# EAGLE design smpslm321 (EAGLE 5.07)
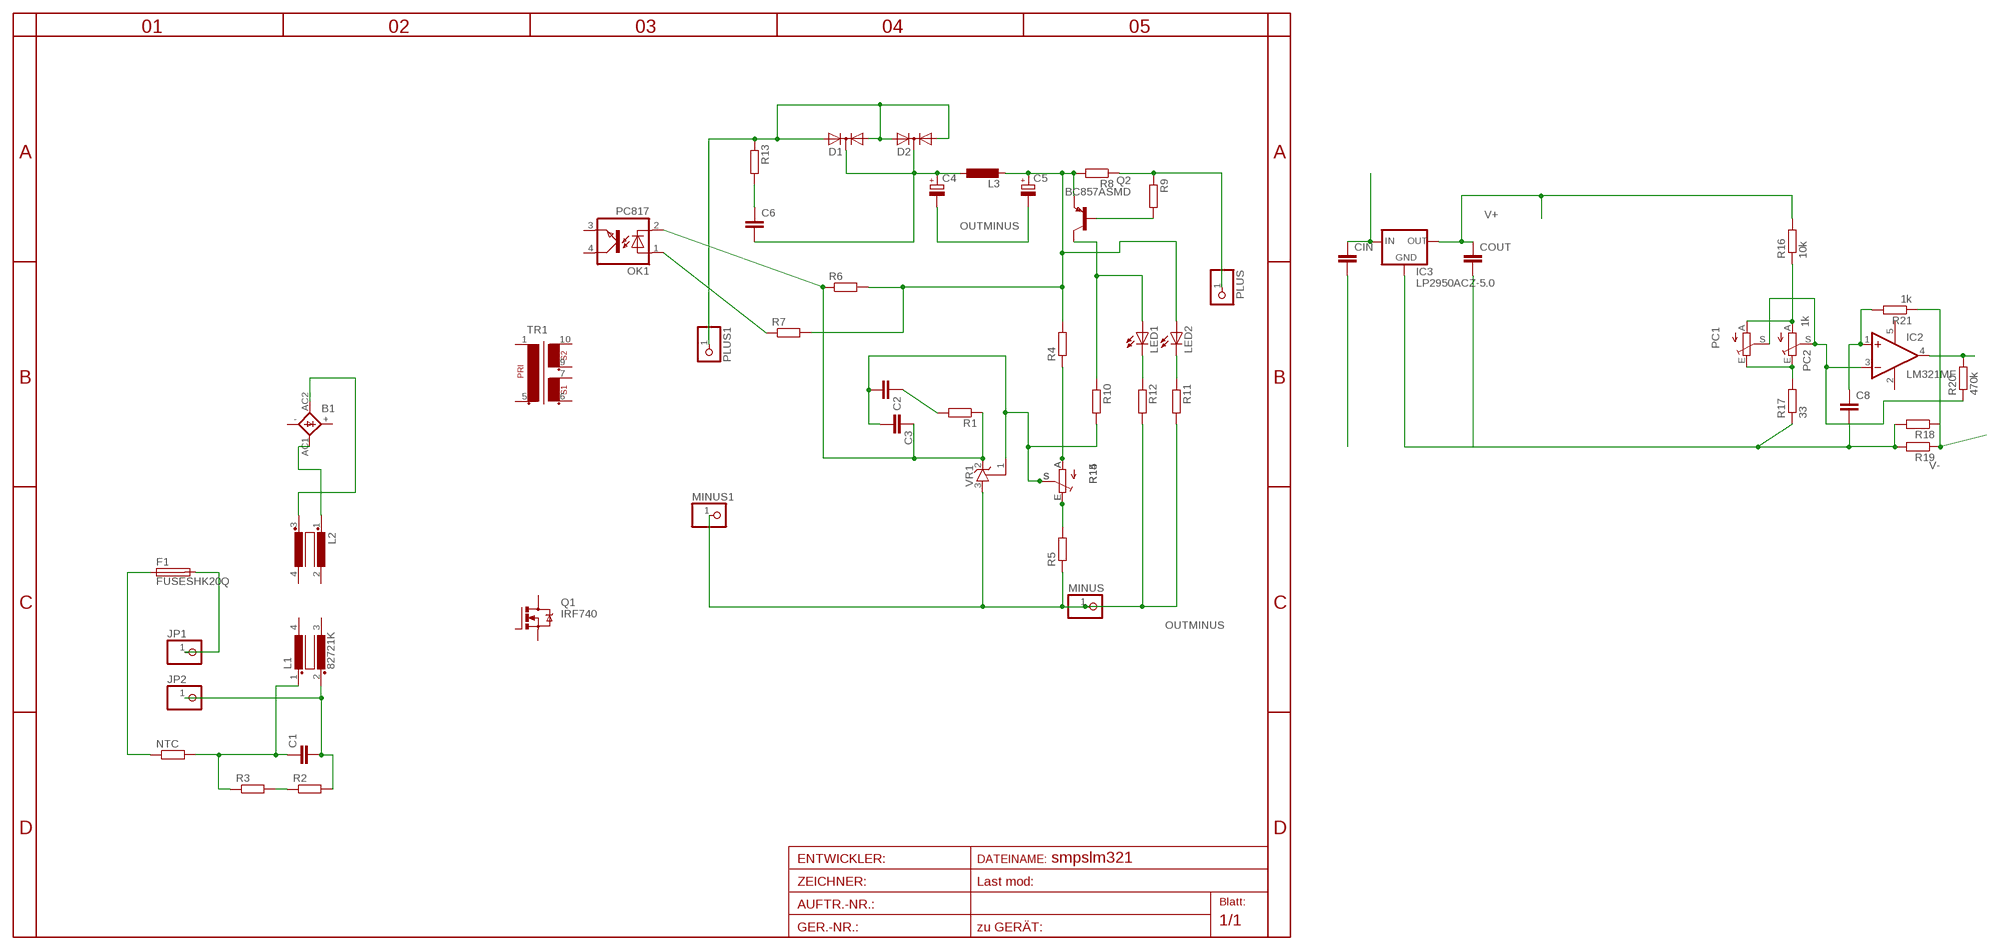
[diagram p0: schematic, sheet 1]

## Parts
B1  KBL  [KBL]
C1  C-EU150-084X183  [C150-084X183]
C2  C-EUC0805  [C0805]
C3  C-EUC0805  [C0805]
C4  CPOL-EUE5-8.5  [E5-8,5]
C5  CPOL-EUE5-8.5  [E5-8,5]
C6  C-EUC0805  [C0805]
C8  C-EUC0805  [C0805]
CIN  C-EUC1206  [C1206]
COUT  C-EUC1206  [C1206]
D1  DIODE-2AC|CAIW220V  [IW220ABS]
D2  DIODE-2AC|CAIW220V  [IW220ABS]
F1  FUSESHK20Q  [SHK20Q]
IC2  LM321MF  [SOT23-5]
IC3  LP2950ACZ-5.0  [TO92]
JP1  PINHD-1X12MM2  [1X2MM2]
JP2  PINHD-1X12MM2  [1X2MM2]
L1  82721K  [82721K]
L2  R1405VB1  [B1]
L3  L-EU0204/5  [0204/5]
LED1  LED3MM  [LED3MM]
LED2  LED3MM  [LED3MM]
MINUS  PINHD-1X12MM2  [1X2MM2]
MINUS1  PINHD-1X11X0.4  [1X01]
NTC  R-EU_0204/7  [0204/7]
OK1  PC817  [DIL04]
PC1  TRIM_EU-S64W  [S64W]
PC2  1k  TRIM_EU-CA6V  [CA6V]
PLUS  PINHD-1X12MM2  [1X2MM2]
PLUS1  PINHD-1X11X0.4  [1X01]
Q1  IRF740  [TO220BV]
Q2  BC857ASMD  [SOT23-BEC]
R1  R-EU_R0805  [R0805]
R2  R-EU_R1206  [R1206]
R3  R-EU_R1206  [R1206]
R4  R-EU_R0805  [R0805]
R5  R-EU_R0805  [R0805]
R6  R-EU_R0805  [R0805]
R7  R-EU_R0805  [R0805]
R8  R-EU_R2010  [R2010]
R9  R-EU_R0805  [R0805]
R10  R-EU_R0805  [R0805]
R11  R-EU_R0805  [R0805]
R12  R-EU_R0805  [R0805]
R13  R-EU_R0805  [R0805]
R14  TRIM_EU-S64W  [S64W]
R15  TRIM_EU-CA6V  [CA6V]
R16  10k  R-EU_R0805  [R0805]
R17  33  R-EU_R1206  [R1206]
R18  R-EU_R2010  [R2010]
R19  R-EU_R2010  [R2010]
R20  470k  R-EU_R0805  [R0805]
R21  1k  R-EU_R0805  [R0805]
TR1  EE20-2  [EE30GREEN]
VR1  TL431CLPSOT23  [SOT23]

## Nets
A: R4.1 R14.A R15.A
A1: PC1.A PC2.A R16.1
CPLUS: C4.+ C6.2 D1.C D2.C L3.1
E: R5.2 R14.E R15.E
E1: PC1.E PC2.E R17.2
N$1: C1.2 JP2.1 L1.2 R2.2
N$2: C1.1 L1.1 NTC.2 R3.1
N$3: F1.2A JP1.1
N$4: IC2.4(OUT) R20.2
N$5: C8.1 IC2.1(+IN) R21.2
N$6: R2.1 R3.2
N$7: B1.AC2(AC1) L2.3
N$8: B1.AC1(AC2) L2.1
N$9: F1.1A NTC.1
N$11: C3.1 OK1.2(C) R1.1 R6.1 VR1.2(C)
N$12: OK1.1(A) R7.1
N$13: C2.1 R1.2
N$14: D1.A1 D1.A2 D2.A1 D2.A2 PLUS1.1 R13.1
N$16: Q2.B R9.2
N$17: LED1.A Q2.C R10.1
N$21: LED1.K(C) R12.1
N$23: LED2.K(C) R11.1
N$27: C6.1 R13.2
OUT: R18.1 R19.1 R21.1
OUTMINUS: C4.- C5.- MINUS1.1 MINUS.1 R5.1 R11.2 R12.2 VR1.3(A)
OUTPLUS: CIN.1 IC3.3(IN) PLUS.1 R8.1 R9.1
PLUS2: C5.+ L3.2 LED2.A Q2.E R4.2 R6.2 R7.2 R8.2
S: C2.2 C3.2 R10.2 R14.S R15.S VR1.1(R)
S1: IC2.3(-IN) PC1.S PC2.S R20.1
V+: COUT.1 IC3.1(OUT) R16.2
V-: C8.2 CIN.2 COUT.2 IC3.2(GND) R17.1 R18.2 R19.2
Unconnected: B1.+ B1.- L1.3 L1.4 L2.2 L2.4 OK1.3(EMIT) OK1.4(COL) Q1.D Q1.G Q1.S TR1.1 TR1.5 TR1.6 TR1.7 TR1.9 TR1.10

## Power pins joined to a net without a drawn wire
V+: IC2.5(V+)
V-: IC2.2(V-)

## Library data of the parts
B1 = rectifier:KBL: DIOTEC RECTIFIER
C1-C3 C6 C8 CIN COUT = rcl:C-EU: CAPACITOR, European symbol
C4 C5 = rcl:CPOL-EU: POLARIZED CAPACITOR, European symbol
D1 D2 = diode:DIODE-2AC|CA: Dual DIODE Anode-Cathode|Cathode-Anode
F1 = fuse:FUSE: Fuse
IC2 = linear:LM321?*: Low Power Single Op Amp Source: http://cache.national.com/ds/LM/LM321.pdf
IC3 = v-reg:LP2950?*: Source: http://cache.national.com/ds/LP/LP2950.pdf
JP1 JP2 MINUS MINUS1 PLUS PLUS1 = pinhead:PINHD-1X1: PIN HEADER
L1 = inductors:82721K: FILTER
L2 = inductor-nkl:R1405V: Übertrager (verlustarm) bis typ. 400kHz Power transformer (low loss) up to typ. 400kHz
L3 = rcl:L-EU: INDUCTOR, European symbol
LED1 LED2 = led:LED: LED
NTC R1-R13 R16-R21 = rcl:R-EU_: RESISTOR, European symbol
OK1 = optocoupler:PC817: SHARP OPTO COUPLER
PC1 PC2 R14 R15 = pot:TRIM_EU-: POTENTIOMETER
Q1 = transistor-power:IRF740: N-CHANNEL MOS FET
Q2 = transistor-pnp:BC857*: PNP Transistror
TR1 = trafo:EE20-2: TRANSFORMER 1 primary winding, 2 secondary windings ERA
VR1 = v-reg:TL431CLP: VOLTAGE REGULATOR

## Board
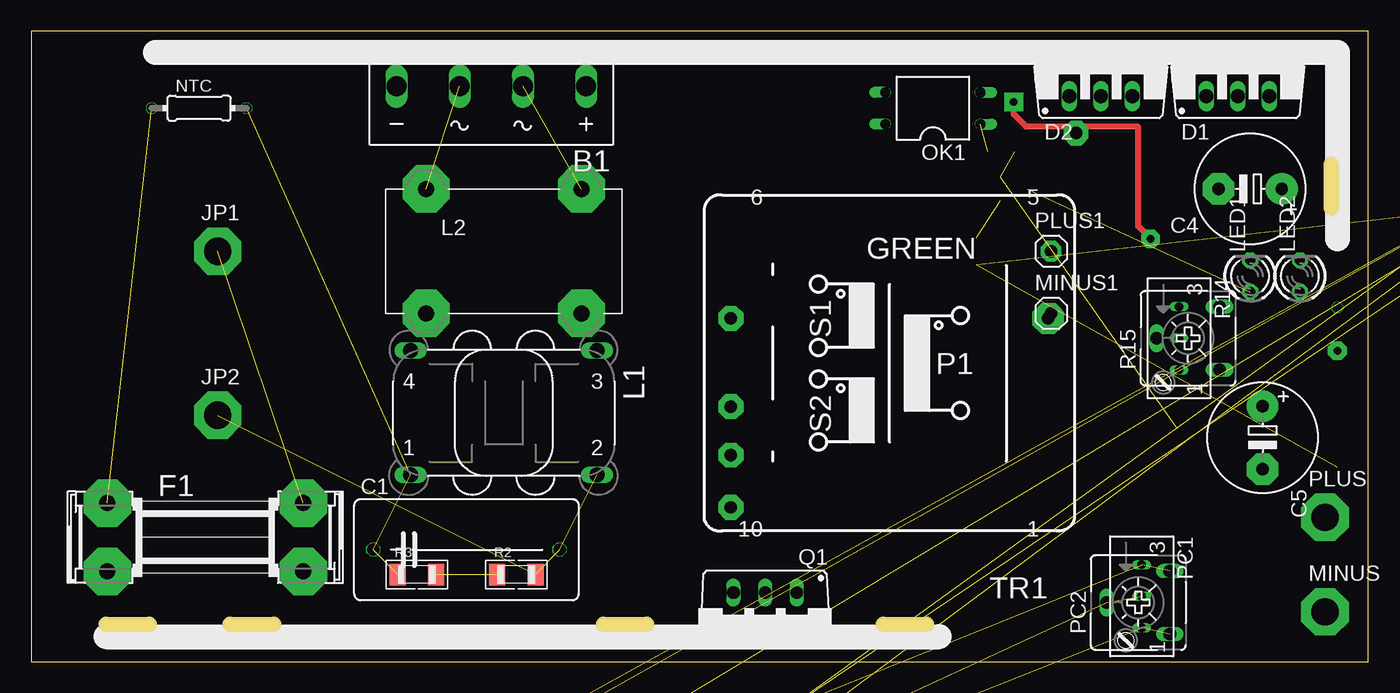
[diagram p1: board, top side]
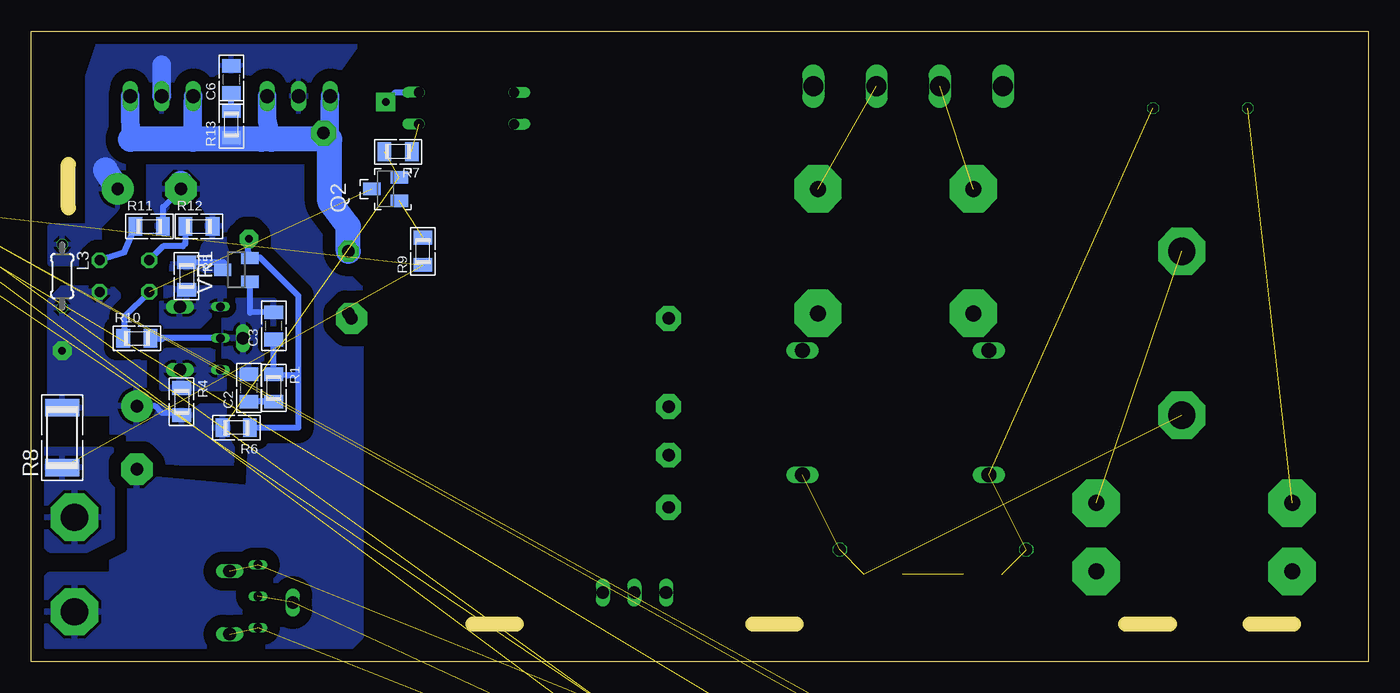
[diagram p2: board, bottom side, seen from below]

Size 107.5 x 50.7 mm. Coordinates in mm from the lower left corner, seen from the top.
Outline: 0,0 107.5,0 107.5,50.7 0,50.7 0,0
Copper layers (1*16): Top 0.035mm / dielectric 1.5mm / Bottom 0.035mm
Design rules "default": minimum track width 10mil, minimum drill 20mil, track to track 8mil, track to pad 8mil, pad to pad 8mil, via to via 8mil, smd to smd 8mil, copper to edge 40mil, drill to drill 8mil, minimum pad ring 1mil, minimum via ring 8mil, stop-mask expansion 4mil, vias tented up to drill 0mil, thermal gap 10mil
Milling: 5 lines

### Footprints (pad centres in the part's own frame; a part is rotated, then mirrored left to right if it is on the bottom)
KBL = drill 1.6 long: + -7.62,-1.27; - 7.62,-1.27; AC1 2.54,-1.27; AC2 -2.54,-1.27
C150-084X183 = drill 1.016 octagon: 1 -7.493,0; 2 7.493,0
C0805 = smd 1.1 x 1.5: 1 -1.1,0; 2 1.1,0
E5-8,5 = drill 1 pad 2.54 round: + -2.54,0 | drill 1 pad 2.54 octagon: - 2.54,0
C1206 = smd 1.6 x 1.8: 1 -1.4,0; 2 1.4,0
IW220ABS = drill 1.118 long: A1 -2.54,-2.54; A2 2.54,-2.54; C 0,-2.54
SHK20Q = drill 1.3 pad 3.81 octagon: 1A -7.874,2.75; 1B -7.874,-2.75; 2A 7.874,2.75; 2B 7.874,-2.75
SOT23-5 = smd 0.6 x 1.2: 1 -0.95,-1.306; 2 0,-1.306; 3 0.95,-1.306; 4 0.95,1.306; 5 -0.95,1.306
TO92 = drill 0.813 octagon: 1 -1.27,0; 2 0,1.905; 3 1.27,0
1X2MM2 = drill 2.2 pad 3.81 octagon: 1 0,0
82721K = drill 1.194 long: 1 7.493,5.004; 2 -7.493,5.004; 3 -7.493,-5.004; 4 7.493,-5.004
B1 = drill 1.27 pad 3.81 octagon: 1 -6.25,5; 2 -6.25,-5; 3 6.25,5; 4 6.25,-5
0204/5 = drill 0.813 octagon: 1 -2.54,0; 2 2.54,0
LED3MM = drill 0.8 pad 1.27 octagon: A -1.27,0; K 1.27,0
1X01 = drill 1 pad 1.676 octagon: 1 0,0
0204/7 = drill 0.813 octagon: 1 -3.81,0; 2 3.81,0
DIL04 = drill 0.813 offset: 1 -1.27,-3.81; 2 1.27,-3.81; 3 1.27,3.81; 4 -1.27,3.81
S64W = drill 0.7 long: A 2.54,1.27; E -2.54,1.27; S 0,1.27
CA6V = drill 1.016 long: A -2.54,-2.54; E 2.54,-2.54; S 0,2.54
TO220BV = drill 1.016 long: D 0,-2.54; G -2.54,-2.54; S 2.54,-2.54
SOT23-BEC = smd 1 x 1.4: B -0.95,-1.1; C 0,1.1; E 0.95,-1.1
R0805 = smd 1.1 x 1.5: 1 -1.1,0; 2 1.1,0
R1206 = smd 1.3 x 1.7: 1 -1.55,0; 2 1.55,0
R2010 = smd 1.4 x 2.7: 1 -2.4,0; 2 2.4,0
EE30GREEN = drill 1 pad 2 octagon: 1 15,18.5; 6 -12.75,3.6; 7 -12.75,-3.5; 9 -12.75,-7.4; 10 -12.75,-11.6 | drill 1 pad 2.5 octagon: 5 12.75,3.6
SOT23 = smd 1 x 1.4: 1 -0.95,-1.1; 2 0.95,-1.1; 3 0,1.1

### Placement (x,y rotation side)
B1  37,45 180 top
C1  35,9 0 top
C2  90,22 90 bottom
C3  88,27 90 bottom
C4  98,38 180 top
C5  99,18 270 top
C6  91.4,46.8 90 bottom
C8  not placed on the board
CIN  not placed on the board
COUT  not placed on the board
D1  97,48 0 top
D2  86,48 0 top
F1  14,10 0 top
IC2  not placed on the board
IC3  not placed on the board
JP1  15,33 0 top
JP2  15,19.8 0 top
L1  38,20 180 top
L2  38,33 0 top
L3  105,31 270 bottom
LED1  98,31 90 top
LED2  102,31 90 top
MINUS  104,4 0 top
MINUS1  82,28 0 top
NTC  13.5,44.5 0 top
OK1  72.5,44.5 90 top
PC1  88,5.25 270 top
PC2  89,4.75 90 top
PLUS  104,11.6 0 top
PLUS1  82,33 0 top
Q1  59,3 180 top
Q2  79,38 90 bottom
R1  88,22 270 bottom
R2  39,7 0 top
R3  31,7 0 top
R4  95.4,20.9 270 bottom
R5  95,31 270 bottom
R6  91,18.8 180 bottom
R7  78,41 180 bottom
R8  105,18 90 bottom
R9  76,33 90 bottom
R10  99,26 0 bottom
R11  98,35 0 bottom
R12  94,35 0 bottom
R13  91.4,43.2 90 bottom
R14  91,26 270 top
R15  93,26 90 top
R16  not placed on the board
R17  not placed on the board
R18  not placed on the board
R19  not placed on the board
R20  not placed on the board
R21  not placed on the board
TR1  69,24 0 top
VR1  91,31.5 90 bottom

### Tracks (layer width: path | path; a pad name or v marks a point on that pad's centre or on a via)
A
  pour Bottom (isolate 0.5, rank 2): 92,25 97,25 97,24 97,22 92,22
A1  (2 unrouted)
CPLUS
  Bottom 1.5: D1.C 97,48
  Bottom 2: C4.+ 101.54,39.54
  pour Bottom (isolate 1): 81,50 102,50 103,47 103,35 106,35 106,32 103,32 102,33 102,35 100,37 100.1,42.8 86.1,42.8
E
  pour Bottom (isolate 0.5, rank 2): 93,28 92,28 92,30 97,30 97,27 94,27
E1  (2 unrouted)
N$1  (3 unrouted)
N$2  (3 unrouted)
N$3  (1 unrouted)
N$4  (1 unrouted)
N$5  (2 unrouted)
N$6  (1 unrouted)
N$7  (1 unrouted)
N$8  (1 unrouted)
N$9  (1 unrouted)
N$11  (via drill 0.6 pad 1.5)
  Top 0.5: v79,45 79,44 80,43 89,43 89,35 v90,34
  Bottom 0.5: R6.1 86,18.8 86,23 | 86,23 86.9,23 R1.1 C3.1 | v90,34 90.05,32.95 VR1.2 90.25,32.4 89.1,32.5 86,29.4 86,23 | OK1.2 78.23,45.77 v79,45
N$12  (1 unrouted)
N$13
  Bottom 0.5: R1.2 88.85,20.9 C2.1
N$14
  Bottom 0.5: R13.1 89.1,41.9 89,42
  Bottom 1.5: 83.5,42 83.5,44.82 D2.A1 | D2.A2 88.54,43.54 88.2,42 | 94.5,42 94.5,44.9 D1.A1 | D1.A2 99.54,44.54 99.5,42
  Bottom 2: PLUS1.1 82,35 83.5,37 83.5,42 88.2,42 89,42 94.5,42 99.5,42
N$16  (1 unrouted)
N$17  (1 unrouted)
  Bottom 0.5: 100.1,25.9 R10.1 100,26 100,27.73 LED1.A
N$21
  Bottom 0.5: R12.1 95.1,33.6 95.3,33.4 96.87,33.4 LED1.K
N$23
  Bottom 0.5: LED2.K 100,32.9 R11.1
N$27
  Bottom 0.5: R13.2 C6.1
OUT  (2 unrouted)
OUTMINUS
  Bottom 0.5: R11.2 96.9,36.56 C4.- | R5.1 92.1,32.1 92,32 92,32.1 VR1.3
  Bottom 2: C4.- 95.46,38.46
  pour Bottom (isolate 1, rank 3): 98,40 84,40 84,33 81,30 81,2 82,1 106,1 107,2 107,6 106,7 101,7 101,15 90,14 89,31 96,31 98,36
OUTPLUS  (3 unrouted)
  pour Bottom (isolate 1): 107,17 107,10 106,9 103,9 101,10 101,17
PLUS2  (via drill 0.6 pad 1.5)  (2 unrouted)
  Bottom 0.5: C5.+ 97.54,20.54 97,20 96.1,20 R4.2 95.9,20
  other vias: 105,25
  pour Bottom (isolate 1, rank 4): 101,30 105,30 106,29 106,21 105,20 101,20 101,16 91,16 91,26 100,26 100,29
S
  Bottom 0.5: C3.2 89.9,28.05 VR1.1 | R14.S 97,26 97,25.9 R10.2
  pour Bottom (isolate 0.5): 88,29 92,29 92,23 88,23
S1  (3 unrouted)
V+  (3 unrouted)
V-  (7 unrouted)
